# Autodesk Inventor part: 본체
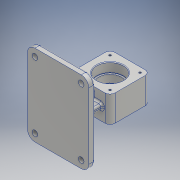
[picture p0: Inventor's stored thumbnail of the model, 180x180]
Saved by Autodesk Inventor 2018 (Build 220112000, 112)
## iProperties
Created: 2020-11
Part Number: 본체
Material: 알루미늄 6061
Document SubType Name: Modeling
Designer: Administrator
Density: 2.7 g/cm^3
Appearance: 알루미늄 - 평지
Mass: 683.422 g
Surface Area: 543.19 cm^2
Volume: 253.119 cm^3
Author: Administrator
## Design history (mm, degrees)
sketch "스케치4"
  geometry: L1 (-32, 32)-(32, 32); L2 (32, 32)-(32, -32); L3 (32, -32)-(-32, -32); L4 (-32, -32)-(-32, 32); L5 (-32, 32)-(32, -32); L6 (32, 32)-(-32, -32); 1 further point
  constraints: 12 end point, 2 midpoint, 2 parallel, 1 horizontal, 1 perpendicular
  dimensions: "d6" = 64 distance of L2.end L3.end; "d7" = 64 distance of L1.end L2.end
extrude "돌출2" new body sketch "스케치4" stored distance "d8" = 42; taper "d9" = 0 deg
sketch "스케치5"
  geometry: L1 (32, 21)-(-32, 21) reference; L2 (0, 21)-(21, 21); L3 (21, 21)-(21, 6); L4 (21, 6)-(0, 6); L5 (0, 6)-(0, 21); L6 (0, 6)-(18, 6); L7 (18, 6)-(18, -6); L8 (18, -6)-(0, -6); L9 (0, -6)-(0, 6); L10 (-32, -21)-(32, -21) reference; L11 (0, -6)-(21, -6); L12 (21, -6)-(21, -21); L13 (21, -21)-(0, -21); L14 (0, -21)-(0, -6); 1 further point
  constraints: 24 end point, 6 parallel, 3 horizontal, 3 perpendicular, 2 point on line, 1 midpoint
  dimensions: "d10" = 42 diameter of L3 L5; "d11" = 36 diameter of L7 L9; "d12" = 15 distance of L2.end L3.end; "d13" = 15 distance of L11.end L12.end
revolve "회전1" sketch "스케치5" stored, may be unused: angle "d14" = 90 deg
node "작업 평면1"
sketch "스케치6"
  geometry: L1 (62, 65)-(-36, 65); L2 (-36, 65)-(-36, -65); L3 (-36, -65)-(62, -65); L4 (62, -65)-(62, 65); L5 (62, 65)-(-36, -65); L6 (-36, 65)-(62, -65); L7 (32, -21)-(32, 21) reference; L8 (-32, 21)-(32, 21) reference; L9 (-32, 21)-(-32, -21) reference; L10 (32, -21)-(-32, -21) reference; 3 further points
  constraints: 12 end point, 3 midpoint, 2 parallel, 1 horizontal, 1 horizontal alignment, 1 perpendicular
  dimensions: "d16" = 130 distance of L1.end L2.end; "d17" = 98 distance of L2.end L3.end; "d18" = 62 distance from line of point (0, 0) L4
extrude "돌출3" join sketch "스케치6" distance "d19" = 10; taper "d20" = 0 deg
sketch "스케치7"
  geometry: L1 (-4, -17)-(4, -17); L2 (4, -17)-(4, 17); L3 (4, 17)-(-4, 17); L4 (-4, 17)-(-4, -17); L5 (-4, -17)-(4, 17); L6 (4, -17)-(-4, 17); L7 (20, 4)-(-20, 4); L8 (-20, 4)-(-20, -4); L9 (-20, -4)-(20, -4); L10 (20, -4)-(20, 4); L11 (20, 4)-(-20, -4); L12 (-20, 4)-(20, -4); 1 further point
  constraints: 24 end point, 4 midpoint, 4 parallel, 2 horizontal, 2 perpendicular
  dimensions: "d21" = 8 distance of L3.end L2.end; "d22" = 34 distance of L2.end L1.end; "d23" = 40 distance of L9.end L8.end; "d24" = 8 distance of L8.end L7.end
extrude "돌출4" join sketch "스케치7" stored distance "d25" = 10; taper "d26" = 0 deg
fillet "모깎기1" dims "d27" = 12
fillet "모깎기2" dims "d28" = 3
fillet "모깎기3" dims "d29" = 3
fillet "모깎기4" dims "d30" = 8
sketch "스케치8"
  geometry: L1 (-24, 24)-(24, 24); L2 (24, 24)-(24, -24); L3 (24, -24)-(-24, -24); L4 (-24, -24)-(-24, 24); L5 (-24, 24)-(24, -24); L6 (24, 24)-(-24, -24); 2 further points
  constraints: 12 end point, 2 midpoint, 2 parallel, 1 coincident, 1 horizontal, 1 perpendicular
  dimensions: "d31" = 48 distance of L2.end L3.end; "d32" = 48 distance of L1.end L2.end
hole "구멍1" sketch "스케치8" at (-24, 24) diameter "d33" = 3.242; stored, may be unused: countersink angle "d37" = 90 deg, drill point angle "d39" = 118 deg; dims "d34" = 8, "d35" = 4, "d36" = 2, "d38" = 10
sketch "스케치9"
  geometry: L1 (-24, 24)-(24, 24); L2 (24, 24)-(24, -24); L3 (24, -24)-(-24, -24); L4 (-24, -24)-(-24, 24); L5 (-24, 24)-(24, -24); L6 (24, 24)-(-24, -24); 2 further points
  constraints: 12 end point, 2 midpoint, 2 parallel, 1 coincident, 1 horizontal, 1 perpendicular
  dimensions: "d43" = 48 distance of L2.end L3.end; "d44" = 48 distance of L1.end L2.end
hole "구멍2" sketch "스케치9" at (-24, 24) diameter "d45" = 3.242; stored, may be unused: countersink angle "d49" = 90 deg, drill point angle "d51" = 118 deg; dims "d46" = 8, "d47" = 4, "d48" = 2, "d50" = 10
sketch "스케치10"
  geometry: C1 r 4.5 at (24, 53); C2 r 4.5 at (-50, 53); A1 r 12 centre (24, 53) between (36, 53) and (24, 65) reference; A2 r 12 centre (-50, 53) between (-50, 65) and (-62, 53) reference; 1 further point
  constraints: 2 centre point, 2 coincident
  dimensions: "d55" = 4.5 radius of C1; "d56" = 4.5 radius of C2
extrude "돌출5" cut sketch "스케치10" extent not by distance; stored distance "d57" = 10; taper "d58" = 0 deg
fillet "모깎기5" dims "d59" = 0.3
fillet "모깎기6" dims "d60" = 1
sketch "스케치14"
  geometry: L1 (24, 65)-(-50, 65) reference; L2 (-62, 53)-(-62, -53) reference; 2 further points
  constraints: 1 other
  dimensions: "d61" = 65 distance from line of L1 point (-52, 0); "d62" = 10 distance from line of L2 point (-52, 0)
feature "엠보싱1" sketch "스케치14" dims "d6" = 64, "d7" = 64, "d12" = 15, "d63" = 0.5, "d64" = 0
node "솔리드2"
pattern_circular "원형 패턴1" dims angle "d41" = 360 deg
pattern_circular "원형 패턴2" dims angle "d53" = 360 deg
mirror "미러1"
node "투영된 루프1"
